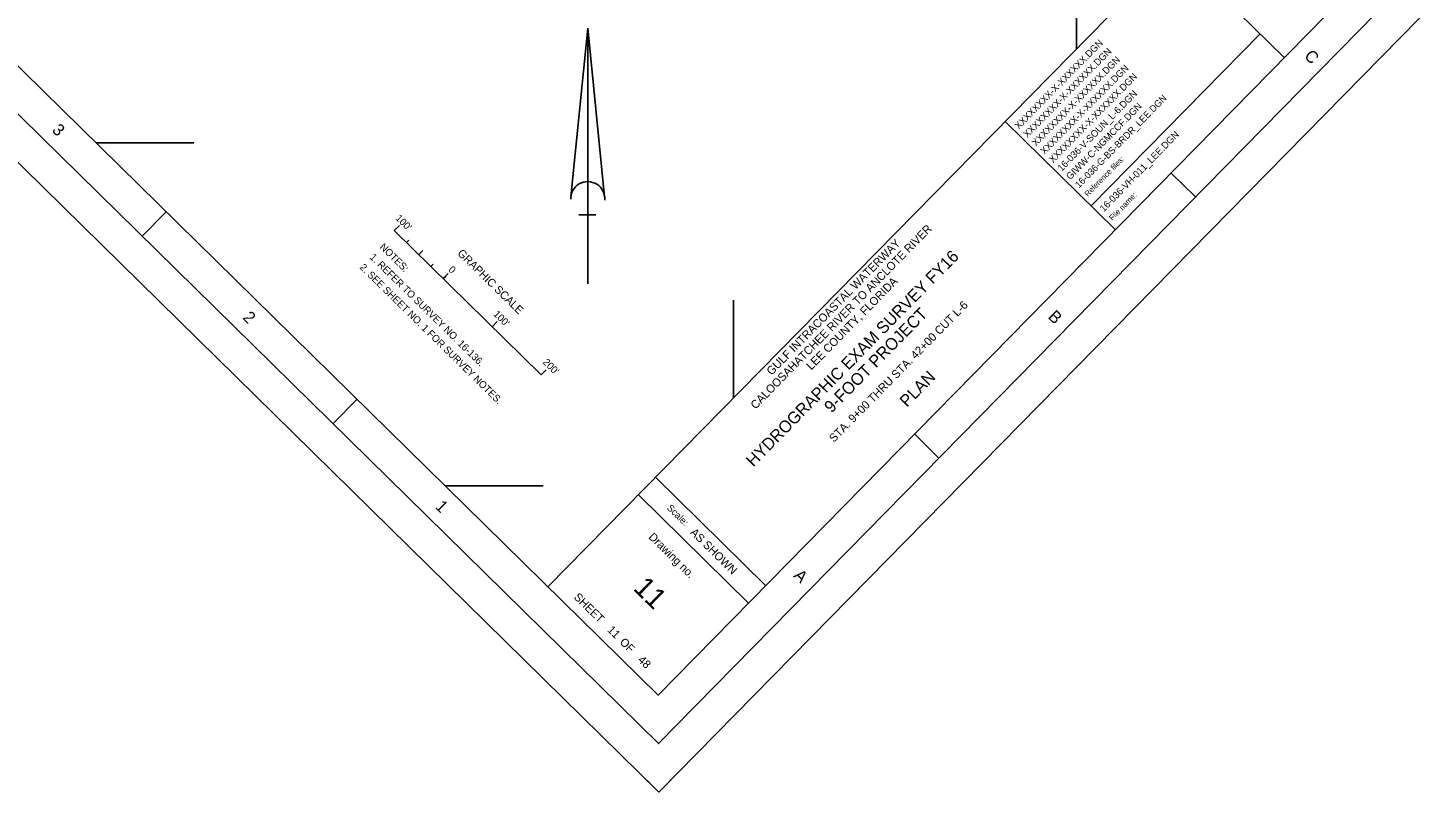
# Model space of a CAD drawing. Extents: x 617253 to 622774, y 776554 to 782063.
# Drawn here: x 619472 to 621498, y 776554 to 777668 of the extents above; entities that cross this region are included whole.
import ezdxf

# ---------------------------------------------------------------- set-up
doc = ezdxf.new("R2010")
doc.units = 0
for name, color, linetype in [('G-ANNO-NPLT', 7, 'Continuous'), ('G-ANNO-TEXT-DRWG', 7, 'Continuous'), ('G-ANNO-TEXT-PROJ', 7, 'Continuous'), ('G-ANNO-TEXT-TTLB', 7, 'Continuous'), ('G-ANNO-TTLB', 7, 'Continuous'), ('V-ANNO-NOTE', 7, 'Continuous'), ('V-ANNO-SYMB', 7, 'Continuous'), ('V-TOPO-COOR-STAT', 7, 'Continuous')]:
    doc.layers.add(name, color=color, linetype=linetype)

msp = doc.modelspace()

# ---------------------------------------------------------------- linework, layer by layer
at = {"layer": 'G-ANNO-NPLT'}
msp.add_lwpolyline([(619635.8, 782062.9), (622774.3, 778979.1), (620391.4, 776554), (617252.9, 779637.7)], close=True, dxfattribs=at)
msp.add_lwpolyline([(620426.5, 776589.5), (620391.5, 776553.9), (620355.8, 776588.9)], dxfattribs=at)
at = {"layer": 'G-ANNO-TTLB'}
for p, q in [((622472.4, 779135.6), (620229.7, 776853.1)), ((621141.4, 777782.7), (621302.8, 777624.2)), ((621267.6, 777658.7), (621021.4, 777408.1)), ((620896, 777531.2), (621056.5, 777373.5)), ((621173.4, 777421.1), (621137.7, 777456.2)), ((619638.3, 777364.1), (619673.3, 777399.7)), ((619916.5, 777090.7), (619951.5, 777126.4)), ((620799.6, 777040.7), (620763.9, 777075.8)), ((620386.5, 777012.7), (620547, 776855)), ((620361.5, 776987.2), (620522, 776829.5))]:
    msp.add_line(p, q, dxfattribs=at)
for points in [[(617323.6, 779638.4), (620390.8, 776624.7), (622703.6, 778978.5), (619636.5, 781992.2)], [(622632.9, 778977.9), (619690.6, 781868.9), (617447.8, 779586.4), (620390.2, 776695.4)]]:
    msp.add_lwpolyline(points, close=True, dxfattribs=at)
at = {"layer": 'V-ANNO-NOTE'}
for p, q in [((620005.8, 777372.2), (620013.2, 777379.7)), ((620005.8, 777372.2), (620219.8, 777161.9)), ((620023.7, 777354.7), (620027, 777358.1)), ((620041.5, 777337.2), (620047.5, 777343.2)), ((620059.3, 777319.6), (620062.7, 777323.1)), ((620077.2, 777302.1), (620084.5, 777309.6)), ((620077.2, 777302.1), (620084.5, 777309.6)), ((620077.2, 777302.1), (620080.7, 777305.7)), ((620148.5, 777232), (620155.8, 777239.5)), ((620219.8, 777161.9), (620227.1, 777169.4))]:
    msp.add_line(p, q, dxfattribs=at)
at = {"layer": 'V-ANNO-SYMB'}
for p, q in [((620263, 777421.1), (620287.7, 777666.9)), ((620287.7, 777294.5), (620287.7, 777666.9)), ((620312.4, 777421.1), (620287.7, 777666.9)), ((620299.5, 777395.1), (620274.6, 777395.1))]:
    msp.add_line(p, q, dxfattribs=at)
msp.add_arc((620287.7, 777418.7), 24.8, 355.2984, 182.0673, dxfattribs=at)
at = {"layer": 'V-TOPO-COOR-STAT'}
for p, q in [((621000, 777637.1), (621000, 777779.8)), ((619571.3, 777500), (619713.9, 777500)), ((620500, 777128.2), (620500, 777270.9)), ((620080.1, 777000), (620222.8, 777000))]:
    msp.add_line(p, q, dxfattribs=at)

# ---------------------------------------------------------------- texts
at = {"layer": 'G-ANNO-TEXT-DRWG'}
for s, height, rotation, p in [('XXXXXXXX-X-XXXXXX.DGN', 10, 45.5037, (620916, 777519.1)), ('XXXXXXXX-X-XXXXXX.DGN', 10, 45.5037, (620928.5, 777506.8)), ('XXXXXXXX-X-XXXXXX.DGN', 10, 45.5037, (620941, 777494.6)), ('XXXXXXXX-X-XXXXXX.DGN', 10, 45.5037, (620953.5, 777482.3)), ('XXXXXXXX-X-XXXXXX.DGN', 10, 45.5037, (620965.9, 777470.1)), ('16-036-V-SOUN_L-6.DGN', 10, 45.5037, (620978.4, 777457.8)), ('GIWW-C-NGMCCF.DGN', 10, 45.5037, (620990.9, 777445.5)), ('16-036-VH-011_LEE.DGN', 10, 45.5037, (621039.9, 777398.8)), ('STA. 9+00 THRU STA. 42+00 CUT L-6', 12, 45.5037, (620646.6, 777062.8)), ('PLAN', 17.5, 45.5037, (620753, 777113.8)), ('11', 30, 315.5037, (620352.7, 776849.6)), (' 11          48', 12, 315.5037, (620312.2, 776792.3))]:
    msp.add_text(s, height=height, rotation=rotation, dxfattribs=at).set_placement(p)
at = {"layer": 'G-ANNO-TEXT-PROJ'}
for s, height, p in [('16-036-G-BS-BRDR_LEE.DGN', 9.8, (621003.8, 777433.4)), ('CALOOSAHATCHEE RIVER TO ANCLOTE RIVER', 12, (620532.3, 777111.1)), ('GULF INTRACOASTAL WATERWAY', 12, (620555.6, 777160.5)), ('HYDROGRAPHIC EXAM SURVEY FY16', 17.5, (620529.1, 777026.9)), ('LEE COUNTY, FLORIDA', 12, (620613.6, 777168.1)), ('9-FOOT PROJECT', 17.5, (620643, 777105.4))]:
    msp.add_text(s, height=height, rotation=45.5037, dxfattribs=at).set_placement(p)
at = {"layer": 'G-ANNO-TEXT-TTLB'}
for s, height, rotation, p in [('Reference files:', 8, 45.5037, (621016.5, 777421.1)), ('File name:', 8, 45.5037, (621052.3, 777386.2)), ('Scale:', 10, 315.5037, (620402.3, 776967.2)), ('AS SHOWN', 12, 315.5037, (620436.1, 776931.3)), ('Drawing no.', 12, 315.5037, (620375.5, 776924.7)), ('SHEET         OF', 12, 315.5037, (620266.5, 776837.1))]:
    msp.add_text(s, height=height, rotation=rotation, dxfattribs=at).set_placement(p)
at = {"layer": 'G-ANNO-TTLB'}
for s, p in [('C', (621330.8, 777625.2)), ('3', (619506, 777517.4)), ('2', (619784, 777244.2)), ('B', (620957.4, 777245.5)), ('1', (620064.4, 776968.7)), ('A', (620586.8, 776868.3))]:
    msp.add_text(s, height=17.5, rotation=315.5037, dxfattribs=at).set_placement(p)
at = {"layer": 'V-ANNO-NOTE'}
for s, height, p in [("100'", 10.42, (620006.7, 777389.2)), ('NOTES:', 10.42, (619983.8, 777347.3)), ('GRAPHIC SCALE', 11.666, (620096.9, 777338.1)), ('2. SEE SHEET NO. 1 FOR SURVEY NOTES.', 10.416, (619954.6, 777317.6)), ('1. REFER TO SURVEY NO. 16-136.', 10.416, (619969.2, 777332.4)), ('0', 10.4, (620083.9, 777314.3)), ("100'", 10.42, (620149.4, 777249.5)), ("200'", 10.42, (620221.5, 777179.4))]:
    msp.add_text(s, height=height, rotation=315.5037, dxfattribs=at).set_placement(p)

doc.saveas('drawing.dxf')
